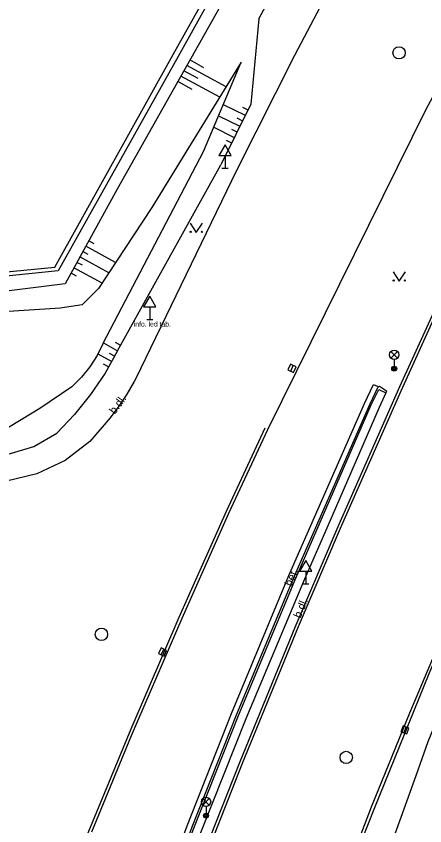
# Model space of a CAD drawing. Extents: x -599951 to -598963, y -1164095 to -1162939.
# Drawn here: x -599123.8 to -599090.7, y -1163520.6 to -1163454.9 of the extents above; entities that cross this region are included whole.
import ezdxf

# ---------------------------------------------------------------- set-up
doc = ezdxf.new("R2010")
doc.units = 0
for name, color, linetype in [('Level 10', 7, 'Continuous'), ('Level 11', 7, 'Continuous'), ('Level 14', 7, 'Continuous'), ('Level 15', 7, 'Continuous'), ('Level 27', 7, 'Continuous'), ('Level 33', 7, 'Continuous'), ('Level 34', 7, 'Continuous'), ('Level 36', 7, 'Continuous'), ('Level 40', 7, 'Continuous'), ('Level 42', 7, 'Continuous'), ('Level 7', 7, 'Continuous')]:
    doc.layers.add(name, color=color, linetype=linetype)

msp = doc.modelspace()

# ---------------------------------------------------------------- linework, layer by layer
at = {"layer": 'Level 10'}
for points in [[(-599117.65, -1163521.09), (-599114.44, -1163513.27), (-599110.34, -1163503.76), (-599106.54, -1163495.23), (-599103.39, -1163488.42), (-599090.5, -1163462.37), (-599077.66, -1163438.76), (-599074.812, -1163433.995), (-599062.63, -1163413.61), (-599055.4, -1163402.34), (-599053.01, -1163398.74)], [(-599139.38, -1163477.16), (-599128.22, -1163475.98), (-599120.64, -1163475.24), (-599111.07, -1163457.98), (-599101.3, -1163440.49), (-599098.73, -1163435.9), (-599095.61, -1163430.32), (-599094.65, -1163428.55), (-599093.67, -1163426.81), (-599088.68, -1163417.86), (-599084.69, -1163410.72), (-599084.25, -1163409.97), (-599084.5, -1163407.96), (-599084.75, -1163405.96), (-599085.26, -1163400.92)], [(-599047.86, -1163401.99), (-599050.23, -1163405.73), (-599057.47, -1163417.43), (-599062.46, -1163425.89), (-599072.58, -1163443.64), (-599087.83, -1163474.25), (-599089.79, -1163478.58), (-599092.69, -1163484.97), (-599097.7, -1163496.33)], [(-599113.68, -1163483.48), (-599105.88, -1163467.37), (-599101.2, -1163458.05), (-599096.77, -1163449.64), (-599091.05, -1163439.23)], [(-599113.68, -1163483.48), (-599114.21, -1163484.53), (-599114.81, -1163485.55), (-599115.46, -1163486.53), (-599116.17, -1163487.48)], [(-599116.17, -1163487.48), (-599117.82, -1163489.4), (-599119.82, -1163490.94), (-599122.11, -1163492.04), (-599124.57, -1163492.63)], [(-599083.36, -1163492.14), (-599087.28, -1163501.09), (-599090.33, -1163508.27), (-599094.74, -1163519.15), (-599098.11, -1163527.68), (-599101.95, -1163537.83), (-599102.52, -1163539.41), (-599103.03, -1163541.06)], [(-599097.7, -1163496.33), (-599101.18, -1163504.5), (-599105.65, -1163515.42), (-599108.56, -1163522.79), (-599112.67, -1163533.66), (-599115.92, -1163542.44), (-599118.17, -1163548.8), (-599119.97, -1163554.03), (-599122.34, -1163561.22), (-599124.91, -1163569.39), (-599126.83, -1163575.79), (-599128.48, -1163581.37), (-599129.72, -1163585.79), (-599133.24, -1163599), (-599135.77, -1163608.36), (-599139.28, -1163623.33), (-599143.16, -1163642.62), (-599149.778, -1163679.861), (-599149.81, -1163680.07), (-599149.87, -1163680.38)]]:
    msp.add_lwpolyline(points, dxfattribs=at)
at = {"layer": 'Level 11'}
for points in [[(-599129.46, -1163585.79), (-599129.17, -1163584.69), (-599128.52, -1163582.5), (-599127.9, -1163580.23), (-599127.35, -1163578.36), (-599126.62, -1163575.83), (-599124.05, -1163567.47), (-599121.41, -1163559.32), (-599119.31, -1163552.96), (-599116.19, -1163543.96), (-599112.48, -1163533.74), (-599109.15, -1163524.96), (-599105.44, -1163515.53), (-599100.89, -1163504.43), (-599097.49, -1163496.43), (-599092.56, -1163485.28), (-599089.53, -1163478.6), (-599088.89, -1163477.22)], [(-599076.7, -1163477.22), (-599079.5, -1163483.17), (-599087.27, -1163500.53), (-599091.9, -1163511.47), (-599094.99, -1163519.09), (-599103.34, -1163540.98), (-599103.03, -1163541.06)], [(-599130.42, -1163582.5), (-599130.86, -1163582.38), (-599129.13, -1163576.79), (-599126.25, -1163567.2), (-599123.26, -1163557.7), (-599120.14, -1163548.49), (-599116.8, -1163538.96), (-599109.92, -1163520.6), (-599106.33, -1163511.48), (-599101.68, -1163500.29), (-599095.53, -1163486.32), (-599094.82, -1163484.77), (-599094.42, -1163484.94)], [(-599094.42, -1163484.94), (-599095.13, -1163486.43), (-599101.29, -1163500.46), (-599105.94, -1163511.62), (-599109.54, -1163520.72), (-599116.42, -1163539.07), (-599119.74, -1163548.62), (-599122.85, -1163557.82), (-599125.87, -1163567.31), (-599128.76, -1163576.91), (-599130.42, -1163582.5)], [(-599094.42, -1163484.94), (-599094.31, -1163484.91), (-599093.75, -1163485.29), (-599093.8, -1163485.44)], [(-599129.58, -1163582.61), (-599130.21, -1163582.43), (-599128.6, -1163576.97), (-599125.71, -1163567.35), (-599122.7, -1163557.86), (-599119.61, -1163548.67), (-599116.27, -1163539.13), (-599109.39, -1163520.79), (-599105.77, -1163511.65), (-599101.12, -1163500.5), (-599094.99, -1163486.44), (-599094.39, -1163485.17)], [(-599093.8, -1163485.44), (-599094.35, -1163486.65), (-599098.516, -1163496.238), (-599100.49, -1163500.78), (-599105.16, -1163511.91), (-599108.78, -1163521.05), (-599109.88, -1163523.83), (-599114.68, -1163536.74), (-599115.65, -1163539.35), (-599119, -1163548.9), (-599120.54, -1163553.48), (-599120.63, -1163553.44), (-599120.73, -1163553.73), (-599120.63, -1163553.76), (-599122.05, -1163558.04), (-599125.09, -1163567.56), (-599127.96, -1163577.16), (-599129.58, -1163582.61)], [(-599094.39, -1163485.17), (-599093.8, -1163485.44)], [(-599135.66, -1163570.66), (-599135.87, -1163570.61), (-599130.56, -1163554.17), (-599125.43, -1163540.14), (-599120.37, -1163527.12), (-599117.89, -1163521.03), (-599114.47, -1163512.74), (-599110.58, -1163503.67), (-599106.74, -1163495.06), (-599103.6, -1163488.3)]]:
    msp.add_lwpolyline(points, dxfattribs=at)
at = {"layer": 'Level 14'}
for points in [[(-599095.06, -1163430.66), (-599098.38, -1163437.77), (-599106.77, -1163453.2), (-599115.6, -1163468.93), (-599119.82, -1163476.61)], [(-599104.1, -1163455.09), (-599095.81, -1163439.61)], [(-599104.1, -1163455.09), (-599104.77, -1163462.02), (-599107.2, -1163466.95)], [(-599116.74, -1163481.43), (-599108.6, -1163465.85), (-599105.54, -1163458.62), (-599112.78, -1163470.4), (-599117.11, -1163476.98), (-599118.43, -1163478.3), (-599120.21, -1163478.58), (-599130.67, -1163479.25), (-599135.41, -1163479.67)], [(-599115.57, -1163482.03), (-599107.2, -1163466.95)], [(-599071.78, -1163472.35), (-599077.24, -1163484.32), (-599080.18, -1163490.78), (-599087.78, -1163507.52), (-599088.21, -1163508.46), (-599090.41, -1163513.8), (-599091.37, -1163516.54), (-599093.93, -1163523.61), (-599095.36, -1163527.1), (-599098.69, -1163534.45), (-599098.76, -1163534.58), (-599101.86, -1163541.43), (-599101.91, -1163541.56), (-599102.7, -1163543.51), (-599103.3, -1163545.12), (-599103.92, -1163547.46), (-599103.98, -1163547.82), (-599104.26, -1163551), (-599104.27, -1163551.48), (-599104.25, -1163552.82), (-599103.98, -1163558.19), (-599103.78, -1163560.52), (-599102.39, -1163567.31)], [(-599119.82, -1163476.61), (-599130.2, -1163477.9)], [(-599116.74, -1163481.43), (-599117.23, -1163482.41), (-599117.82, -1163483.33), (-599118.5, -1163484.19), (-599119.27, -1163484.97)], [(-599115.57, -1163482.03), (-599116.58, -1163483.86), (-599117.75, -1163485.59), (-599119.05, -1163487.22)], [(-599119.27, -1163484.97), (-599121.86, -1163486.73), (-599125.04, -1163488.66)], [(-599119.05, -1163487.22), (-599120.48, -1163488.74)], [(-599122.37, -1163489.8), (-599120.48, -1163488.74)], [(-599124.45, -1163490.44), (-599122.37, -1163489.8)]]:
    msp.add_lwpolyline(points, dxfattribs=at)
at = {"layer": 'Level 15'}
for points in [[(-599108.56, -1163459.06), (-599109.71, -1163458.43)], [(-599109.03, -1163459.94), (-599110.2, -1163459.3)], [(-599106.76, -1163460.6), (-599109.95, -1163458.87)], [(-599107.28, -1163461.46), (-599110.44, -1163459.74)], [(-599109.51, -1163460.82), (-599110.69, -1163460.18)], [(-599106.99, -1163462.04), (-599105.21, -1163462.92)], [(-599105.44, -1163462.25), (-599104.99, -1163462.47)], [(-599107.38, -1163462.96), (-599105.65, -1163463.81)], [(-599105.88, -1163463.14), (-599105.43, -1163463.37)], [(-599107.77, -1163463.89), (-599106.1, -1163464.71)], [(-599106.32, -1163464.04), (-599105.88, -1163464.26)], [(-599106.77, -1163464.94), (-599106.32, -1163465.16)], [(-599117.46, -1163473.35), (-599117.89, -1163473.1)], [(-599115.72, -1163474.87), (-599118.13, -1163473.54)], [(-599116.27, -1163475.71), (-599118.62, -1163474.42)], [(-599117.94, -1163474.22), (-599118.38, -1163473.98)], [(-599118.42, -1163475.1), (-599118.86, -1163474.86)], [(-599118.9, -1163475.97), (-599119.34, -1163475.73)], [(-599116.82, -1163476.54), (-599119.1, -1163475.3)], [(-599116.72, -1163481.39), (-599115.57, -1163482.03)], [(-599115.76, -1163481.35), (-599115.33, -1163481.59)], [(-599117.16, -1163482.29), (-599116.04, -1163482.91)], [(-599116.25, -1163482.22), (-599115.8, -1163482.47)], [(-599116.74, -1163483.1), (-599116.28, -1163483.35)]]:
    msp.add_lwpolyline(points, dxfattribs=at)
at = {"layer": 'Level 27'}
for p, q in [((-599101.527, -1163483.686), (-599101.313, -1163483.234)), ((-599112.027, -1163506.716), (-599111.813, -1163506.264)), ((-599092.347, -1163513.054), (-599092.173, -1163512.586))]:
    msp.add_line(p, q, dxfattribs=at)
for points in [[(-599101.3, -1163483.793), (-599101.087, -1163483.34), (-599101.54, -1163483.127), (-599101.753, -1163483.58)], [(-599111.8, -1163506.823), (-599111.587, -1163506.37), (-599112.04, -1163506.157), (-599112.253, -1163506.61)], [(-599092.113, -1163513.141), (-599091.939, -1163512.673), (-599092.407, -1163512.499), (-599092.581, -1163512.967)]]:
    msp.add_lwpolyline(points, close=True, dxfattribs=at)
for centre in [(-599092.74, -1163457.85), (-599116.87, -1163505.06), (-599097.02, -1163515.05)]:
    msp.add_circle(centre, 0.5, dxfattribs=at)
at = {"layer": 'Level 33'}
for p, q in [((-599093.395, -1163482.63), (-599092.865, -1163482.1)), ((-599093.395, -1163482.1), (-599092.865, -1163482.63)), ((-599093.13, -1163482.74), (-599093.13, -1163483.49)), ((-599108.655, -1163518.92), (-599108.125, -1163518.39)), ((-599108.655, -1163518.39), (-599108.125, -1163518.92)), ((-599108.39, -1163519.03), (-599108.39, -1163519.78))]:
    msp.add_line(p, q, dxfattribs=at)
for centre, radius in [((-599093.13, -1163482.365), 0.375), ((-599093.13, -1163483.49), 0.2), ((-599093.13, -1163483.49), 0.145), ((-599093.13, -1163483.49), 0.0876), ((-599108.39, -1163518.655), 0.375), ((-599108.39, -1163519.78), 0.2), ((-599108.39, -1163519.78), 0.145), ((-599108.39, -1163519.78), 0.0876)]:
    msp.add_circle(centre, radius, dxfattribs=at)
at = {"layer": 'Level 34'}
for p, q in [((-599106.85, -1163466.182), (-599106.85, -1163467.2)), ((-599107.1, -1163467.2), (-599106.6, -1163467.2)), ((-599112.95, -1163478.472), (-599112.95, -1163479.49)), ((-599113.2, -1163479.49), (-599112.7, -1163479.49)), ((-599100.31, -1163499.942), (-599100.31, -1163500.96)), ((-599100.56, -1163500.96), (-599100.06, -1163500.96))]:
    msp.add_line(p, q, dxfattribs=at)
for points in [[(-599107.35, -1163466.182), (-599106.35, -1163466.182), (-599106.85, -1163465.316)], [(-599113.45, -1163478.472), (-599112.45, -1163478.472), (-599112.95, -1163477.606)], [(-599100.81, -1163499.942), (-599099.81, -1163499.942), (-599100.31, -1163499.076)]]:
    msp.add_lwpolyline(points, close=True, dxfattribs=at)
at = {"layer": 'Level 36'}
for points in [[(-599109.68, -1163471.68), (-599109.18, -1163472.43), (-599108.68, -1163471.68)], [(-599093.22, -1163475.63), (-599092.72, -1163476.38), (-599092.22, -1163475.63)]]:
    msp.add_lwpolyline(points, dxfattribs=at)
for centre in [(-599109.63, -1163472.38), (-599108.731, -1163472.38), (-599093.17, -1163476.33), (-599092.271, -1163476.33)]:
    msp.add_circle(centre, 0.05, dxfattribs=at)
at = {"layer": 'Level 7'}
msp.add_lwpolyline([(-599095.3, -1163430.51), (-599102.16, -1163442.87), (-599110.66, -1163458.14), (-599120.39, -1163475.54), (-599139.14, -1163477.47)], dxfattribs=at)

# ---------------------------------------------------------------- texts
at = {"layer": 'Level 40'}
for s, rotation, p in [('b.dl.', 53.9, (-599115.78, -1163487.24)), ('bet.', 66.45, (-599101.46, -1163501.22)), ('b.dl.', 67.36, (-599100.73, -1163503.8))]:
    msp.add_text(s, height=0.65, rotation=rotation, dxfattribs=at).set_placement(p)
at = {"layer": 'Level 42'}
msp.add_text('info. led tab.', height=0.4, dxfattribs=at).set_placement((-599114.25, -1163480.07))

doc.saveas('drawing.dxf')
